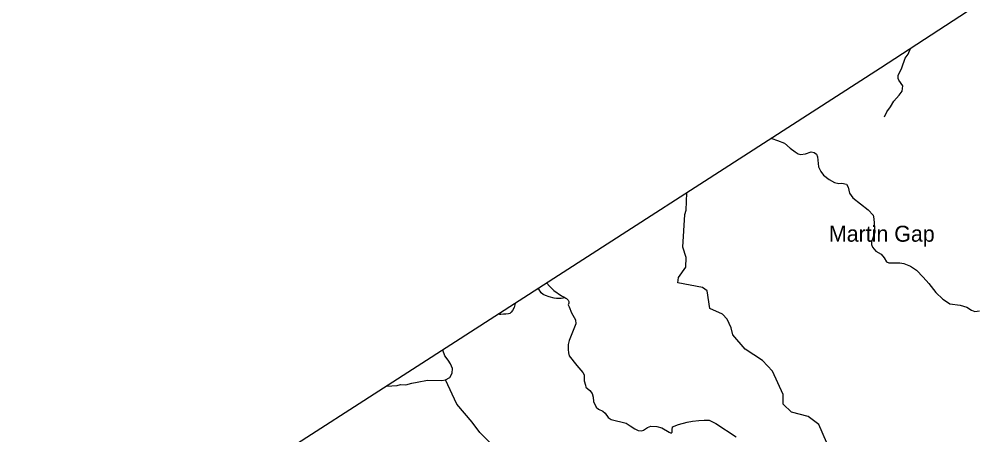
# Model space of a CAD drawing. Extents: x 1248224 to 1454986, y 825081 to 985870.
# Drawn here: x 1248224 to 1261423, y 873913 to 879635 of the extents above; entities that cross this region are included whole.
import ezdxf

# ---------------------------------------------------------------- set-up
doc = ezdxf.new("R2010")
doc.units = 0
for name, color, linetype in [('Exist Boundary Political CountyLine', 7, 'Continuous'), ('Exist Geographical Mountain Summit Label', 7, 'Continuous'), ('Exist Hydrographic Creek Single Shore', 7, 'Continuous'), ('Exist Hydrographic Misc Water Feature', 7, 'Continuous'), ('Exist Road Non-System Type 51', 7, 'Continuous')]:
    doc.layers.add(name, color=color, linetype=linetype)

msp = doc.modelspace()

# ---------------------------------------------------------------- linework, layer by layer
at = {"layer": 'Exist Boundary Political CountyLine'}
msp.add_lwpolyline([(1272546, 896361), (1272209, 895845), (1272087, 895657), (1271079, 894112), (1270645, 893445), (1270071, 892565), (1269839, 892212), (1269310, 891394), (1268930, 890816), (1268447, 890082), (1267988, 889389), (1267175, 888171), (1266759, 887546), (1266505, 887166), (1265873, 886219), (1264802, 884614), (1263985, 883390), (1262147, 880635), (1261769, 880070), (1260071, 878961), (1254161, 875151), (1250985, 873104), (1248224, 871303)], dxfattribs=at)
at = {"layer": 'Exist Hydrographic Creek Single Shore'}
for points in [[(1259326, 873814), (1259224, 874056), (1259077, 874167), (1258845, 874224), (1258731, 874335), (1258734, 874470), (1258584, 874788), (1258446, 874935), (1258208, 875091), (1258038, 875288), (1258016, 875387), (1257961, 875506), (1257896, 875573), (1257723, 875652), (1257687, 875896), (1257622, 875940), (1257281, 876005), (1257292, 876081), (1257395, 876220), (1257399, 876354), (1257352, 876496), (1257381, 876946), (1257399, 877004), (1257409, 877245)], [(1254086, 874671), (1254148, 874701), (1254178, 874761), (1254185, 874826), (1254156, 874889), (1254124, 874942), (1254078, 875002), (1254050, 875080)], [(1254559, 873946), (1254455, 874086), (1254244, 874333), (1254086, 874671)], [(1259148, 873060), (1258688, 873006), (1258465, 873096), (1258323, 873066), (1258153, 872961), (1257945, 872959), (1257885, 872927), (1257837, 872685), (1257812, 872663), (1257746, 872681), (1257077, 873288), (1256776, 873232), (1256518, 873253), (1256092, 873239), (1255554, 873069), (1255404, 873082), (1255280, 873134), (1255118, 873308), (1254974, 873527), (1254559, 873946)]]:
    msp.add_lwpolyline(points, dxfattribs=at)
at = {"layer": 'Exist Hydrographic Misc Water Feature'}
for points in [[(1260125, 878291), (1260158, 878358), (1260210, 878429), (1260252, 878506), (1260326, 878588), (1260370, 878643), (1260380, 878715), (1260324, 878794), (1260314, 878820), (1260315, 878861), (1260364, 878963), (1260411, 879096), (1260451, 879155), (1260481, 879229)], [(1253276, 874581), (1253422, 874593), (1253471, 874608), (1253542, 874603), (1253625, 874622), (1253696, 874640), (1253841, 874667), (1254037, 874659), (1254086, 874671)]]:
    msp.add_lwpolyline(points, dxfattribs=at)
at = {"layer": 'Exist Road Non-System Type 51'}
for points in [[(1258578, 877990), (1258652, 877963), (1258748, 877926), (1258829, 877861), (1258897, 877810), (1258938, 877783), (1258972, 877773), (1259037, 877783), (1259118, 877807), (1259159, 877800), (1259190, 877776), (1259203, 877742), (1259217, 877602), (1259251, 877538), (1259288, 877487), (1259363, 877426), (1259438, 877385), (1259499, 877375), (1259540, 877378), (1259601, 877364), (1259625, 877323), (1259645, 877238), (1259689, 877174), (1259900, 877010), (1259968, 876939), (1259978, 876888), (1259992, 876701), (1259968, 876633), (1259948, 876568), (1259948, 876531), (1259961, 876497), (1260006, 876442), (1260080, 876398), (1260121, 876350), (1260152, 876296), (1260186, 876279), (1260278, 876282), (1260335, 876282), (1260393, 876272), (1260485, 876235), (1260567, 876180), (1260658, 876082), (1260737, 875996), (1260832, 875871), (1260927, 875779), (1260978, 875748), (1261022, 875717), (1261165, 875700), (1261257, 875670), (1261321, 875629), (1261366, 875609), (1261434, 875622)], [(1255483, 876003), (1255518, 875959), (1255577, 875899), (1255685, 875826), (1255728, 875803)], [(1255728, 875803), (1255703, 875793), (1255679, 875791), (1255641, 875791), (1255613, 875790), (1255583, 875795), (1255514, 875814), (1255461, 875831), (1255432, 875845), (1255405, 875867), (1255388, 875890), (1255375, 875908), (1255358, 875923)], [(1255048, 875723), (1255031, 875664), (1255007, 875626), (1254991, 875600), (1254971, 875583), (1254954, 875577), (1254918, 875576), (1254884, 875576), (1254847, 875570), (1254835, 875571), (1254819, 875575)], [(1255728, 875803), (1255742, 875796), (1255754, 875790), (1255774, 875769), (1255785, 875750), (1255782, 875724), (1255777, 875701), (1255787, 875675), (1255821, 875592), (1255856, 875528), (1255877, 875498), (1255880, 875439), (1255863, 875396), (1255788, 875213), (1255774, 875156), (1255776, 875088), (1255778, 875041), (1255788, 875001), (1255896, 874866), (1255978, 874769), (1255997, 874741), (1255997, 874658), (1256011, 874597), (1256020, 874567), (1256072, 874524), (1256105, 874482), (1256119, 874430), (1256124, 874371), (1256161, 874296), (1256190, 874265), (1256251, 874237), (1256284, 874211), (1256324, 874150), (1256366, 874124), (1256573, 874072), (1256627, 874039), (1256691, 873997), (1256738, 873971), (1256787, 873966), (1256811, 873978), (1256867, 874013), (1256914, 874030), (1256992, 874027), (1257065, 874011), (1257164, 873950), (1257193, 873936), (1257207, 873950), (1257207, 873983), (1257212, 874025), (1257290, 874056), (1257410, 874089), (1257485, 874103), (1257570, 874108), (1257647, 874117), (1257715, 874113), (1257807, 874070), (1258085, 873884)]]:
    msp.add_lwpolyline(points, dxfattribs=at)

# ---------------------------------------------------------------- texts
at = {"layer": 'Exist Geographical Mountain Summit Label'}
msp.add_text('Martin Gap', height=220, dxfattribs=at).set_placement((1259361, 876571))

doc.saveas('drawing.dxf')
